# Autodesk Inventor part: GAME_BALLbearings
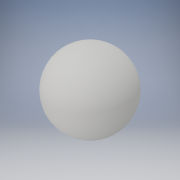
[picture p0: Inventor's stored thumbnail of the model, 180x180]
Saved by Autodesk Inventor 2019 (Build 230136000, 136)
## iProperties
Created: 2020-02
Part Number: GAME_BALLbearings
Material: Generic
Document SubType Name: Modeling
Designer: Siddharth
Density: 1 g/cm^3
Appearance: Default
Author: Siddharth
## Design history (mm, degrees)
sketch "Sketch1"
  geometry: L1 (0, 0)-(29.448, 0); A1 r 13 centre (16.408, 0) between (29.408, 0) and (3.408, 0)
  constraints: 3 point on line, 2 end point, 2 point on circle, 1 centre point, 1 horizontal
  dimensions: "d1" = 90 deg dimension on L1.start L1.end L1 A1.centre A1 A1.end A1.start
revolve "Revolution1" sketch "Sketch1" stored, may be unused: angle "d1" = 90 deg
body "Solid1"
